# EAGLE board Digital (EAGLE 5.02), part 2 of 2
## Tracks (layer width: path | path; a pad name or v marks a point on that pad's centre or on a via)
D0  (2 unrouted)
  Bottom 1.27: IC3.14 38.57,13.33
D1  (2 unrouted)
  Bottom 1.27: IC3.15 38.57,28.57
D2  (2 unrouted)
  Bottom 1.27: IC3.16 36.03,28.44 | 36.03,28.44 36.03,28.57 | 36.03,28.44 36.03,28.82 | 36.03,28.82 36.03,29.2 | 36.03,29.2 36.41,29.2 36.41,29.08 | 36.41,29.08 36.41,28.06 36.16,27.81 36.16,23.62 35.78,23.62 35.78,28.19 35.65,28.32 35.65,28.95 | 35.65,28.95 35.65,29.2 36.03,29.2 | 36.03,29.2 36.16,29.08 | 36.03,28.82 36.03,28.95 35.65,28.95 | 35.65,28.95 35.65,22.98 36.28,22.98 | 36.28,22.98 36.28,29.08 36.41,29.08 | 36.41,29.08 36.41,22.98 36.28,22.98
D3  (2 unrouted)
  Bottom 1.27: IC3.17 33.49,28.57
E  (via drill 0.7 pad 1.68)  (1 unrouted)
  Bottom 1.27: IC3.6 v18.25,13.33
N$1  (1 unrouted)
  Bottom 1.27: R8.1 D2.A 15.71,34.92 | 36.03,14.6 36.03,14.73 | 36.03,14.73 IC3.13 | 36.03,14.73 36.03,13.96 | 36.03,13.96 36.16,13.96 36.28,14.09 36.28,14.6 | 36.28,14.6 36.28,18.16 35.78,18.16 35.78,13.96 36.03,13.96 | 36.03,13.96 36.28,13.96 36.28,14.6
N$2
  Bottom 1.27: 23.58,44.83 23.58,41.91
N$3
  Bottom 0.254: 0.98,63.88 0.98,63.49 0.85,63.49
N$4  (via drill 0.8 pad 1.68)  (1 unrouted)
  Bottom 1.27: R12.2 51.27,1.9 v55.08,1.9
N$5
  Bottom 1.27: 25.87,16.76 25.87,13.33 24.6,12.06 Q1.2 23.33,12.06 23.33,8.25 C1.2 | 25.87,16.76 IC3.9 | 26,16.12 25.62,16.51 25.62,16.63 | 25.62,16.63 25.62,18.16 26.12,18.16 26.12,10.28 25.23,10.28 | 23.58,11.93 23.2,11.93 23.2,13.08 25.87,13.08 25.87,10.28 25.23,10.28 | 25.23,10.28 23.84,10.28 | 25.87,16.76 25.74,16.63 25.62,16.63 | 25.62,16.63 25.62,12.69
N$6  (1 unrouted)
N$7  (1 unrouted)
N$8  (1 unrouted)
N$9  (1 unrouted)
N$10  (via drill 0.7 pad 1.68)  (4 unrouted)
  Bottom 1.27: IC3.27 8.09,26.66 | 8.09,26.66 v8.09,28.57 8.34,28.57 8.34,26.66 | 8.34,26.66 8.34,23.74 7.84,23.74 7.84,24 | 7.84,24 7.84,28.32 | 7.84,28.32 7.84,28.44 | 7.84,28.32 7.84,29.08 | 8.09,26.66 8.34,26.66 | 8.34,26.66 8.34,29.08 7.96,29.08 | 7.96,24 7.84,24 | 7.84,24 7.84,23.49 8.34,23.49
N$11  (1 unrouted)
  Top 1.27: 34.63,64.13 16.98,64.13 16.98,66.42 | 34.63,64.13 34.76,64.13 34.76,66.67 36.03,67.94 IC1.3 | IC2.1 16.98,66.42 | 16.98,70.1 16.6,70.1 | 16.98,70.1 17.61,70.1 17.61,69.97 | 17.61,69.97 17.61,64.26 | 16.98,70.1 16.98,69.72 | 15.96,70.1 16.98,70.1 | 15.96,65.15 15.96,70.1 | 15.96,65.15 15.96,64 19.27,64 | 19.27,64 35.01,64 | 34.63,64.13 34.89,64.13 35.01,64 | 35.01,64 35.01,65.78 | 35.01,65.78 35.01,66.8 35.27,67.05 36.79,67.05 36.79,70.73 35.14,70.73 35.14,67.18 | 16.98,66.42 16.98,66.29 19.27,64 | 17.49,68.83 17.49,69.84 17.61,69.97 | 17.61,69.97 17.61,70.61 15.96,70.61 15.96,70.1 | 15.96,65.15 16.6,65.15 | 15.96,65.15 15.96,62.61 35.27,62.61 35.27,66.42 | 32.73,63.24 35.01,63.24 | 32.73,63.24 16.6,63.24 | 35.01,65.78 35.01,65.53 32.73,63.24
  Bottom 1.27: 9.36,69.21 IC2.1 C4.+ | IC1.3 R2.2
N$12
  Bottom 1.27: 51.78,72 48.09,72 48.09,70.48
N$13
  Bottom 1.27: 24.22,41.78 26.25,41.78 26.25,43.68 25.11,43.68
N$14
  Bottom 1.27: B1.AC2 9.36,62.86 T1.2.MP
N$15
  Bottom 1.27: T2.1.MP 1.74,46.35 B2.AC1 5.55,50.16 R9.2
N$16
  Bottom 1.27: T2.2.MP 1.74,41.27 B2.AC2 6.82,41.27 6.82,41.02 | R8.2 6.82,41.02 | 6.18,41.14 6.69,41.14 6.82,41.02 | 6.82,41.02 6.82,42.41 6.57,42.41 | 6.57,42.41 0.34,42.41 0.34,36.57 7.2,36.57 7.2,42.41 6.57,42.41
N$17
  Bottom 1.27: 11.39,62.61 11.39,63.62
N$18
  Bottom 1.27: R14.1 63.97,67.94 VT2.2
N$19
  Bottom 1.27: IC3.1 R1.2
N$20  (via drill 0.8 pad 1.68)
  other vias: 27.14,50.16
N$21  (via drill 0.8 pad 1.78)
  other vias: 20.54,19.68
N$22
  Bottom 1.27: R11.1 VT2.1
N$23
  Bottom 1.27: VT3.2 60.8,58.41 60.16,57.78 R16.1
N$24  (via drill 0.7 pad 1.68)  (1 unrouted)
  Bottom 1.27: R10.2 58.89,18.41 v58.89,17.14
N$25
  Bottom 1.27: R19.2 VT3.1 60.29,60.32 60.29,60.83 | 60.29,60.83 55.46,60.83 55.46,60.45 56.1,59.81 59.02,59.81 | 59.02,59.81 59.78,59.81 60.16,60.19 | 59.27,60.7 60.16,60.7 60.29,60.83 | 60.29,60.83 60.67,60.83 60.67,60.45 60.03,59.81 59.02,59.81
N$26
  Top 1.27: 48.6,21.84 46.32,21.84
N$27
  Bottom 1.27: R4.2 19.52,41.27 C3.1 B2.+ 11.9,41.27 11.9,41.52 | 11.9,41.52 11.9,41.91 19.52,41.91 20.79,43.17 21.81,43.17 21.81,42.41 20.54,41.14 | 20.54,41.14 20.41,41.02 11.9,41.02 | 11.9,41.52 11.9,40.63 20.03,40.63 20.54,41.14
N$28
  Bottom 1.27: 24.73,50.03 27.01,47.75 27.01,47.62
N$29
  Bottom 1.27: 10.5,24.63 10.5,23.74 | 10.5,23.74 10.88,23.74 10.88,29.08 10.25,29.08 10.25,24.12 | 10.25,24.12 10.25,23.74 10.5,23.74 | 10.25,24.12 10.25,23.49 10.88,23.49
N$30
  Top 1.27: 50.38,52.45 50.38,52.19 53.05,52.19 53.05,54.86 51.27,54.86 | 50.76,54.86 51.27,54.86 | 51.27,54.86 51.27,52.7 49.87,52.7 51.02,52.57
N$31  (via drill 0.7 pad 1.68)  (1 unrouted)
  Bottom 1.27: R15.2 v36.03,4.44
N$32  (via drill 0.8 pad 1.68)  (1 unrouted)
  Top 1.27: R16.2 50.87,52.2 9.26,52.2 9.36,32.38 10.63,31.11 v10.63,28.57 IC3.26
  Bottom 1.27: IC3.26 v10.63,28.57
N$33
  Bottom 1.27: VT1.3 56.35,69.21 R19.1
N$34
  Bottom 1.27: IC1.2 33.49,65.4 R3.2
N$35
  Bottom 1.27: 13.17,28.7 13.17,29.08 13.42,29.08 13.42,23.62 12.92,23.62 | 12.92,23.62 12.92,29.08 | 13.17,24 13.17,23.87 12.92,23.62 | 12.92,23.62 12.92,23.36 13.42,23.36
N$36
  Bottom 1.016: VT1.1 51.4,69.21 51.4,66.16 D1.C
N$37
  Bottom 1.27: 24.6,42.54 R4.1 | IC3.23 18.25,36.19 24.6,42.54 | 24.6,42.54 24.6,45.08 23.33,46.35 R5.2
N$38
  Bottom 1.27: 28.41,23.87 28.54,23.87 28.54,28.7 28.16,28.7 28.16,28.57 | 28.16,28.57 28.16,24.63 | 28.16,24.63 28.16,23.87 28.28,23.87 | 28.16,24.63 28.16,22.98 28.66,22.98 28.66,28.57 | 28.66,28.57 28.66,28.7 | 28.66,28.57 28.66,29.2 28.16,29.2 28.16,28.57
N$39
  Bottom 1.27: 48.48,71.24 51.4,71.24
N$40
  Bottom 1.27: VT5.1 R.EXTERNAL.MP | R.EXTERNAL.MP D9.A | R23.2 R.EXTERNAL.MP
N$41
  Bottom 0.406: R3.1 40.98,65.4 43.65,69.08 43.65,72.26 | 43.52,72.26 43.65,72.26 | 43.65,72.26 43.65,72.51
  Bottom 1.016: 43.27,72.25 43.27,66.16 D1.A
  Bottom 1.27: R3.1 41.11,65.4 | 31.08,68.7 31.08,67.56 29.55,67.56 29.55,72 30.95,72 | 30.95,72 43.27,72.25 43.52,72.26 | 30.95,72 IC1.1
N$43
  Bottom 1.27: R7.1 6.82,32.38 JP1.2
N$44
  Bottom 1.27: IC3.18 30.95,26.79 | 30.95,26.79 30.95,26.92 | 30.95,26.92 R13.2 | 30.95,26.92 31.08,26.92 31.08,28.44 | 31.08,28.44 31.08,23.87 30.7,23.87 30.7,28.7 31.08,28.7 31.08,28.44 | 30.95,26.79 30.95,23.49 31.08,23.49 31.08,22.98 30.57,22.98 30.57,28.7 | 30.57,28.7 31.2,28.7 31.2,28.44 | 31.2,28.44 31.2,22.98 30.44,22.98 30.44,28.32 | 30.44,28.32 30.44,28.7 30.57,28.7 | 31.08,28.44 31.2,28.44 | 31.2,28.44 31.2,29.2 30.44,29.2 30.44,28.32
N$45
  Bottom 1.27: IC3.28 JP1.1
N$46
  Bottom 1.27: R18.2 IC3.19
N$47
  Bottom 1.27: 38.44,28.32 38.44,23.49 39.84,23.49 39.84,28.06 38.7,29.2 38.19,29.2 38.19,27.93
N$48  (via drill 0.7 pad 1.68)  (1 unrouted)
  Bottom 1.27: R17.1 v65.24,17.14
N$49  (via drill 0.7 pad 1.68)  (1 unrouted)
  Bottom 1.27: R23.1 v60.16,28.57
N$50  (via drill 0.7 pad 1.68)  (1 unrouted)
  Bottom 1.27: VT6.1 v51.27,17.14
N$51  (via drill 0.7 pad 1.68)  (1 unrouted)
  Bottom 1.27: R24.1 68.54,41.27 | 68.54,41.27 v69.05,41.27 | 68.54,41.27 70.45,41.27
N$52  (via drill 0.7 pad 1.68)  (1 unrouted)
  Bottom 1.27: IC3.2 v8.09,13.33
N$53
  Bottom 1.27: 23.2,16.38 23.2,15.87 | 23.2,15.87 23.2,15.74 23.58,15.74 23.58,20.06 | 23.2,15.87 23.08,15.74 22.95,15.74 22.95,19.93
N$54  (via drill 0.8 pad 1.93)
  other vias: 38.57,28.57
N$55
  Bottom 1.27: R2.1 39.84,52.7 K1.1
N$56  (via drill 0.8 pad 1.93)
  other vias: 36.03,28.57
N$57  (via drill 0.8 pad 1.93)
  Bottom 1.27: v33.49,28.57 33.49,29.2 33.62,29.2 | 33.62,29.2 33.87,28.95 33.87,28.82 | 33.87,28.82 33.87,28.32 | 33.87,28.32 33.87,27.93 33.74,27.81 33.74,27.55 33.62,27.43 33.62,23.49 33.11,23.49 33.11,24.89 | 33.11,24.89 33.11,29.2 33.62,29.2 | 33.62,28.32 33.87,28.32 | 33.87,28.32 33.87,27.55 | 33.11,24.89 33.11,22.98 33.87,22.98 33.87,28.82 | 33.87,28.82 33.87,29.2
N$58  (via drill 0.8 pad 1.68)
  other vias: 56.35,6.98
N$59  (via drill 0.8 pad 1.93)
  other vias: 69.05,51.43
N$60  (via drill 0.8 pad 1.93)
  other vias: 1.74,-9.53 1.74,-9.53 1.74,-9.53 1.74,-9.53 1.74,-9.53 1.74,-9.53 61.43,36.19
N$61  (via drill 0.8 pad 1.68)
  other vias: 15.71,28.57
N$62  (via drill 0.7 pad 1.68)
  other vias: 38.57,13.33
N$63  (via drill 0.7 pad 1.68)
  other vias: 15.71,34.92
N$64  (via drill 0.7 pad 1.68)
  other vias: 36.03,14.6
N$65  (via drill 0.7 pad 1.68)
  other vias: 33.49,14.6
N$66  (via drill 0.7 pad 1.68)
  other vias: 43.65,41.27 37.3,41.27
N$67  (via drill 0.7 pad 1.78)
  other vias: 69.05,48.89
N$68
  Bottom 1.27: 0.34,65.27 3.14,65.27 4.03,64.38 10.38,64.38 | 10.38,64.38 10.5,64.38 | 3.77,62.35 3.9,62.48 10.5,62.48 10.5,64.38 | 3.77,62.35 2.76,61.34 0.22,61.34 0.22,65.15 0.47,65.15 1.49,64.13 8.22,64.13 8.85,63.49 3.52,63.49 2.12,62.1 | 10,64.26 10.12,64.38 10.38,64.38 | 10.5,64.38 12.15,64.38 12.15,62.35 3.77,62.35
N$69  (1 unrouted)
  Bottom 1.27: 10.38,59.94 4.66,59.94 | 4.66,59.94 4.41,59.68 | 5.04,59.56 4.66,59.94 | 10.63,59.94 10.63,58.67 10.5,58.67 | 10.5,58.67 4.92,58.67 3.77,57.53 3.77,53.46 0.34,53.46 0.34,59.05 2.12,58.8 2.12,59.05 | T1.1.MP 1.74,59.05 2.12,59.05 | 2.12,59.05 3.77,59.05 | 3.77,59.05 9.36,59.05 | 2.12,59.05 0.6,59.05 | 4.66,59.94 3.77,59.05 | 8.6,58.92 10.5,58.92 10.5,58.67 | 10.5,58.67 12.03,58.67 12.03,60.07 4.79,60.07
N$70
  Bottom 1.27: 10.88,59.68 11.52,59.68 11.52,59.43
N$71
  Bottom 1.27: 1.1,58.29 1.1,54.35 2.76,54.35 2.88,54.48 2.88,58.16 2.76,58.29 3.26,58.29 3.39,58.16
N$72
  Bottom 1.27: 2.76,56.13 4.15,56.13 6.95,58.92
N$73
  Bottom 1.27: 7.2,67.18 7.2,67.81 | 7.2,67.81 7.2,70.35 17.11,70.35 17.11,70.23 | 17.11,67.43 17.11,66.54 7.2,66.54 7.2,67.81 | 17.11,70.23 17.11,67.43 | 17.11,67.43 17.11,59.18 | 17.11,70.23 17.11,71.12 7.07,71.12 7.07,66.54
N$74
  Bottom 1.27: 8.22,69.46 8.22,68.7 | 8.22,67.05 8.22,68.7 | 8.22,68.7 8.98,69.46
N$75
  Bottom 1.27: 9.87,68.32 16.22,68.32
N$76
  Bottom 1.27: 16.34,67.43 12.41,67.43 | 12.41,67.43 9.74,67.43 | 15.08,64.89 12.54,67.43 12.41,67.43
N$77
  Bottom 1.27: 16.98,58.16 15.2,58.16 15.2,66.54 15.08,66.67
N$78
  Bottom 1.27: 15.96,65.78 15.96,59.05
N$79
  Bottom 1.27: 20.03,60.7 20.03,55.75
N$80
  Bottom 1.27: 22.31,58.8 22.31,56.13 22.06,55.88 21.3,55.88 21.04,56.13 21.04,58.8 21.17,58.92
N$81
  Bottom 1.27: 11.9,55.88 9.87,55.88
N$82
  Bottom 1.27: 23.2,52.95 11.9,52.95 | 11.9,52.95 9.61,52.95 | 9.61,50.67 11.9,52.95 | 11.9,52.95 10.88,52.95 10.12,52.19
N$83
  Bottom 1.27: 9.61,54.22 22.57,54.22 22.7,54.1
N$84
  Bottom 1.27: 29.81,59.94 29.81,60.32 28.79,61.34 20.03,61.34
N$85
  Bottom 1.27: 20.03,61.84 20.03,71.12 19.52,71.12 | 19.52,71.12 19.39,71.12 19.39,61.34 | 19.52,70.86 19.52,71.12 | 19.52,71.12 19.27,71.12 19.27,62.23 | 19.27,62.23 19.27,61.21 19.77,60.7 | 19.01,56.26 19.27,56.51 19.27,62.23
N$86
  Bottom 1.27: 21.17,60.45 28.92,60.45 28.92,59.81 21.68,59.81
N$87  (1 unrouted)
  Bottom 1.016: 30.19,63.62 32.09,61.72 41.49,61.72 41.49,60.32
  Bottom 1.27: 21.93,70.1 26.12,70.1 26.63,69.59 26.63,68.19 | 26.63,68.19 26.63,65.78 | 26.63,65.78 26.63,64.13 28.16,64.13 | 26.63,68.19 26.63,69.21 IC2.3 22.06,69.84 21.93,69.97 21.93,70.99 27.01,70.99 27.01,66.54 | 28.16,64.13 29.04,64.13 | 29.04,64.13 29.68,64.13 30.19,63.62 27.27,66.54 27.01,66.54 | K1.S2 57.49,49.02 55.08,51.18 55.08,57.78 52.54,60.32 41.49,60.32 41.24,60.32 41.24,61.59 | 21.93,68.19 26.63,68.19 | 27.01,66.54 27.01,64.51 | 26.63,65.78 26.63,65.65 28.16,64.13 | 29.04,64.13 29.04,64.51 27.01,66.54
N$88
  Bottom 1.27: 16.47,54.48 20.54,58.54 20.54,57.02 19.27,55.75
N$89
  Bottom 1.27: 8.73,54.35 8.73,52.57 8.6,52.45
N$90
  Bottom 1.27: 6.95,50.03 6.95,50.16 7.07,50.29 7.2,50.16 7.2,45.21 0.34,45.21 0.34,50.41 6.95,50.41
N$91
  Bottom 1.27: 6.31,49.65 6.31,46.35
N$92
  Bottom 1.27: 1.23,49.91 1.23,48.25 | 1.23,48.25 1.23,47.37 | 1.23,47.37 1.23,46.1 | 5.04,48.25 1.23,48.25 | 1.23,47.37 4.66,47.37
N$93
  Bottom 1.27: 1.74,49.27 4.92,49.27
N$94
  Bottom 1.27: 52.67,38.86 50.13,38.86 50.13,35.94 53.94,35.94 53.94,37.71 52.79,38.86 51.91,38.86 50.89,37.84 50.89,36.7 53.17,36.7 53.3,36.82 52.41,36.82 51.65,37.59
N$95
  Bottom 1.27: 23.46,20.44 45.55,20.44 46.19,21.08 | 46.19,21.08 47.08,21.97 | 46.19,21.08 46.19,22.35 46.06,22.47 46.06,22.6 46.7,22.6
N$96
  Bottom 1.27: 32.22,38.22 23.84,38.22
N$97
  Bottom 1.27: 26.5,46.1 26.5,49.91 26.63,50.03
N$98
  Bottom 1.27: 17.49,46.22 17.49,47.75 10,47.75 10,47.11 16.73,47.11
N$99
  Bottom 1.27: 11.9,50.03 11.77,50.03 | 11.77,50.03 11.52,50.03 11.52,49.52 18.76,49.52 | 11.77,50.03 11.77,50.16 12.54,50.92 19.01,50.92 19.65,50.29
N$100  (via drill 0.7 pad 1.68)  (1 unrouted)
  Bottom 1.27: 19.65,49.91 19.65,44.95 18.5,43.81 17.87,43.81 | R9.1 D3.A 19.52,50.16 19.52,48.64 | 19.52,48.64 19.52,45.08 18.25,43.81 17.87,43.81 | 17.87,43.81 9.36,43.81 9.36,34.92 v11.9,34.92 | IC3.12 33.49,14.6 | 19.52,48.64 18.12,50.03
N$101
  Bottom 1.27: 16.6,37.33 16.6,38.35 11.39,38.35 11.39,37.08 16.6,37.08
N$102
  Bottom 1.27: 15.71,34.67 15.71,34.41 | 15.71,34.41 16.34,34.41 16.34,37.21 | 15.96,34.67 15.71,34.41 | 15.71,34.41 14.57,34.41 14.57,37.21
N$103
  Bottom 1.27: 16.73,37.21 16.73,38.73 11.27,38.73 11.27,37.08
N$104
  Bottom 1.27: 12.03,35.05 12.54,35.05 12.54,34.41 9.36,34.41 9.36,34.92 9.74,35.3 12.54,35.3
N$105
  Bottom 1.27: 5.55,31.36 5.55,30.98 16.22,30.98 16.22,32.25 15.96,32.51 4.15,32.51 4.03,32.38 4.03,30.86 16.22,30.86 16.09,30.98 16.09,31.74 15.96,31.62 5.8,31.62
N$106
  Bottom 1.27: 6.18,28.7 6.06,28.57 6.06,24.12 | 6.06,24.12 6.06,24 4.03,24 4.15,24.12 4.15,28.7 4.79,28.7 | 4.79,28.7 6.31,28.7 6.31,28.06 5.04,28.06 4.79,27.81 4.79,24.51 4.28,24 3.9,24 3.9,28.7 4.79,28.7 | 6.06,24.12 6.06,23.74 3.9,23.74 | 4.28,24.12 3.9,23.74 | 3.9,23.74 3.9,23.49 6.06,23.49
N$107
  Bottom 1.27: 39.08,54.48 40.48,54.48 40.6,54.35 40.6,43.81 40.48,43.68 31.33,43.68 31.2,43.81 31.2,46.98 33.62,46.98
N$108
  Bottom 1.27: 39.46,53.97 32.09,46.6
N$109
  Bottom 1.27: 38.57,51.3 38.57,54.35 38.7,54.48 38.95,54.48
N$110
  Bottom 1.27: 39.84,51.68 39.59,51.43 39.59,44.7 39.46,44.57 32.35,44.57
N$111
  Bottom 1.27: 33.62,45.46 39.33,45.46
N$112
  Bottom 1.27: 39.2,50.67 34.51,45.97
N$113
  Bottom 1.27: 38.7,45.71 38.7,49.02
N$114
  Bottom 1.27: 37.94,48.64 37.43,48.13 37.43,45.97
N$115
  Bottom 1.27: 37.3,45.97 36.28,46.98 35.65,46.98 36.03,46.6 36.03,46.1
N$116
  Bottom 1.27: 68.54,58.03 66.51,60.07 66.51,60.19
N$117
  Bottom 1.27: 24.35,44.95 24.47,45.08 24.47,46.98 24.22,46.98 | 21.55,46.98 23.84,46.98 | 23.84,46.98 23.96,46.98 23.96,45.08 21.42,45.08 21.42,46.98 | 24.22,46.98 23.84,46.98 | 24.22,46.98 24.6,46.98 24.6,44.57 25.74,43.43
N$118
  Bottom 1.27: 22.31,68.58 22.31,68.45 21.93,68.07 21.93,67.43 22.44,66.92 22.44,64 29.43,64
N$119
  Bottom 1.27: 25.62,64.51 25.62,67.56 23.46,67.56 22.95,67.05 22.95,65.4 23.46,64.89 24.6,64.89 24.6,66.67 24.09,66.67 23.84,66.42 23.84,65.53
N$120
  Top 1.27: 50.76,38.09 51.14,38.09
N$121
  Bottom 1.016: 41.36,64.64 41.36,65.02 42.51,66.16
N$122
  Bottom 1.27: 30.31,71.24 30.19,71.12 30.19,68.7 31.2,68.7 | 31.2,68.19 31.2,68.7 | 31.2,68.7 31.2,71.62 | 31.2,68.7 31.2,67.56
N$123
  Bottom 1.27: 35.9,69.84 35.9,68.19 40.48,68.19 40.98,68.7 40.98,70.1 35.9,70.1
N$124
  Bottom 1.27: 51.65,20.44 51.65,21.59 50.38,21.59
N$125
  Bottom 1.27: 32.98,66.04 32.98,70.35 33.87,70.35 | 33.36,69.97 33.36,70.35 33.87,70.35 | 33.87,70.35 33.87,64.64 31.97,64.64 31.46,65.15 31.46,65.91 33.11,65.91 33.36,66.16
N$126
  Bottom 1.27: 32.6,52.95 33.62,52.95 33.74,53.08
N$127
  Bottom 1.27: 51.78,21.59 51.78,20.31 51.14,20.31 | 51.14,20.31 50.89,20.31 50.89,20.82 | 45.55,20.95 51.02,20.95 51.14,20.82 50.89,20.82 | 50.89,20.82 45.05,20.82 | 51.02,20.57 51.02,20.44 51.14,20.31 | 51.14,20.31 46.06,20.31 45.43,20.95
N$128
  Bottom 1.016: 41.49,64 41.49,63.75 43.78,66.04 43.78,72.39
  Bottom 1.27: 36.66,65.78 36.41,65.78 | 36.41,65.78 36.41,63.88 41.36,63.88 41.49,64 42.76,65.27 42.76,67.18 42.13,67.18 42,67.05 42,66.54 41.24,65.78 36.41,65.78 | 36.41,65.78 36.41,66.16 41.11,66.16
N$129
  Bottom 1.27: 41.11,64.51 37.05,64.51
N$130
  Bottom 1.016: 42.63,66.16 42.63,66.67 42.89,66.92 42.89,71.5
N$131
  Bottom 1.016: 43.27,72.26 43.27,68.45 | 43.27,68.45 43.27,65.65 41.36,63.75 | 40.6,65.65 40.6,65.78 43.27,68.45
N$132
  Bottom 1.016: 51.78,66.16 51.78,65.65 51.91,65.53 51.91,65.27 47.97,65.27 47.97,71.5 48.73,71.5 48.73,66.04 49.49,66.04 49.49,67.05 50.76,67.05 50.76,67.18 50.13,67.18 50.13,66.42 50.89,66.42 50.89,70.1
  Bottom 1.27: 50.25,65.4 51.78,66.92 51.78,69.59 | 51.65,69.97 51.78,70.1 51.78,69.59 | 51.78,69.59 51.78,71.88 | 51.78,69.59 51.78,66.16 51.78,65.53
N$133
  Bottom 1.27: 51.78,70.35 48.09,70.35 48.09,67.18
N$134
  Bottom 1.27: 49.11,69.59 49.11,67.56
N$135
  Bottom 1.27: 50.13,69.72 50.13,67.81
N$136
  Bottom 1.27: 50.25,58.16 50.63,57.78 50.63,57.02 50.13,56.51 50.13,48.89
N$137
  Bottom 1.27: 49.62,58.16 49.62,58.29 49.87,58.54 49.37,58.54 | 49.37,58.54 48.73,58.54 48.73,48.89 50.38,48.89 50.51,49.02 50.51,57.78 | 49.24,58.41 49.37,58.54 | 49.37,58.54 51.27,58.54 51.91,57.91 51.91,56 51.65,56 50.63,54.99
N$138
  Bottom 1.27: 49.75,51.18 49.75,49.78 49.49,49.52
N$139
  Bottom 1.27: 51.02,48.76 48.73,48.76
N$140
  Bottom 1.016: 34.63,54.1 34.63,54.22 34.76,54.35 29.3,54.35
N$141
  Bottom 1.27: 56.22,69.97 56.22,70.23 | 56.22,70.23 56.22,70.35 56.35,70.35 | 56.35,70.35 56.48,70.35 56.48,64.89 54.95,64.89 54.95,66.16 55.59,66.16 | 56.22,70.23 56.35,70.35 | 56.35,70.35 55.84,70.35 55.84,66.42
N$142
  Bottom 1.27: 29.17,39.87 33.49,39.87 33.49,36.06 30.31,36.06 | 31.33,37.59 31.71,37.59 32.6,36.7 32.6,36.06 30.31,36.06 | 30.31,36.06 22.31,36.06
N$143
  Bottom 1.27: 31.84,45.33 31.84,45.59 31.97,45.71
N$144
  Bottom 1.27: 31.71,45.59 31.71,44.06 31.2,43.56 31.2,42.29 33.49,42.29 33.49,43.17 32.22,43.17
N$145
  Bottom 1.27: 36.54,41.78 44.41,41.78 | 44.41,41.78 44.54,41.78 44.54,39.62 36.16,39.62 36.16,41.52 | 36.16,41.52 36.16,41.78 44.41,41.78 | 36.28,41.4 36.16,41.52 | 36.16,41.52 36.16,38.48 44.67,38.48 44.67,41.78
N$146
  Bottom 1.27: 36.28,40.51 43.9,40.51
N$147
  Bottom 1.27: 48.98,30.86 48.86,30.86 47.21,32.51
N$148
  Bottom 1.27: 58,55.37 58,56.13 58.51,56.64
N$149
  Bottom 1.27: 59.78,56.64 60.16,56.64 61.05,57.53
N$150
  Bottom 1.27: 44.54,63.24 44.54,63.75 45.17,63.75 | 45.17,63.75 45.81,63.75 45.81,62.23 43.9,62.23 43.9,63.75 45.17,63.75
N$151
  Bottom 1.27: 69.3,70.23 70.95,70.23 70.95,71.75 70.57,71.75 | 70.57,71.75 65.49,71.75 65.49,70.1 70.95,70.1 | 70.57,71.75 71.08,71.75 arc-90 71.21,71.62 71.21,70.1
N$152
  Bottom 1.27: 65.37,67.43 65.37,64.89 62.57,64.89 62.57,68.19 71.21,68.19 71.21,67.69 66.76,67.69 | 66.76,67.69 65.24,67.69 | 65.11,66.04 66.76,67.69
N$153
  Bottom 1.27: 64.86,67.81 64.86,65.4
N$154
  Bottom 1.27: 63.34,67.94 63.34,65.4
N$155
  Bottom 1.27: 58.64,65.02 59.78,65.02 59.78,67.31 59.14,67.31
N$156
  Bottom 1.27: 69.3,65.65 69.56,65.65 | 69.56,65.65 71.34,65.65 71.34,51.05 67.91,51.05 67.91,65.53 | 68.92,64.77 69.56,64.77 69.56,65.65 | 69.56,65.65 68.03,65.65
N$157
  Bottom 1.27: 70.19,65.15 70.19,51.81
N$158
  Bottom 1.27: 69.3,49.27 71.21,49.27 | 71.21,49.27 71.34,49.27 71.34,45.08 67.91,45.08 67.91,49.27 71.21,49.27
N$159
  Bottom 1.27: 70.19,49.02 70.19,45.84
N$160
  Bottom 1.27: 64.86,41.02 64.86,40.13 71.34,40.13 71.34,42.29 64.73,42.29 64.73,40.13
N$161
  Bottom 1.27: 64.35,45.08 65.11,45.08 | 65.11,45.08 65.37,45.08 65.37,57.02 63.59,57.02 63.59,45.08 63.72,45.08 | 63.72,45.08 65.11,45.08 | 63.72,45.59 63.72,45.08 | 63.72,45.08 62.57,45.08 62.57,51.68 63.34,52.45
N$162
  Bottom 1.27: 64.61,56.64 64.61,45.71
N$163
  Bottom 1.27: 62.83,61.46 66.51,61.46 | 66.51,61.46 67.53,61.46 | 68.16,63.11 66.51,61.46
N$164
  Bottom 1.27: 52.67,29.84 52.79,29.84 54.45,31.49
N$165
  Bottom 1.27: 21.3,34.92 23.71,34.92 23.84,34.79
N$166
  Bottom 1.27: 52.16,46.6 52.03,46.6 50,48.64
N$167
  Bottom 1.016: 30.7,54.22 30.7,59.56 30.82,59.68 30.82,55.11 31.84,54.1
N$168
  Bottom 1.27: 57.24,35.17 57.49,35.17 | 57.49,35.17 62.06,35.17 62.06,36.19 61.81,36.44 | 61.81,36.44 61.68,36.57 61.05,36.57 59.4,38.22 59.4,38.86 56.48,38.86 56.48,35.17 57.49,35.17 | 61.56,35.94 61.56,36.19 61.81,36.44 | 61.81,36.44 59.52,38.73
N$169
  Bottom 1.27: 57.37,38.09 58.76,38.09
N$170
  Bottom 1.27: 57.11,36.57 60.16,36.57
N$171
  Bottom 1.27: 61.05,36.06 57.62,36.06
N$172
  Bottom 1.27: 50.63,7.11 50.63,9.65 | 50.63,9.65 50.76,9.77 56.22,9.77 56.22,6.35 50.51,6.35 50.51,9.52 50.63,9.65
N$173
  Bottom 1.27: 51.14,8.63 55.46,8.63
N$174
  Bottom 1.27: 55.46,7.74 51.14,7.74
N$175
  Bottom 1.27: 46.06,6.35 46.19,6.35 | 46.19,6.35 47.08,6.35 47.21,6.47 47.21,10.54 | 47.21,10.54 47.21,13.71 | 47.21,13.71 47.21,14.22 | 47.08,6.47 46.32,6.47 46.19,6.35 | 46.19,6.35 45.3,6.35 45.3,13.84 46.06,14.6 | 47.21,13.71 52.92,13.71 | 48.86,12.69 48.86,12.19 47.21,10.54
N$176
  Bottom 1.27: 63.59,24.25 71.34,24.25 71.34,36.7 64.86,36.7 64.86,24.51
N$177
  Bottom 1.27: 55.46,28.44 61.43,28.44 61.43,27.43 55.21,27.43 55.21,29.2 61.94,29.2 61.94,27.43 59.78,27.43 59.78,27.55
N$178
  Bottom 1.27: 60.8,56.64 60.92,56.51 60.92,53.59 60.8,53.46 59.78,53.46 | 57.37,54.1 57.37,54.48 | 57.37,54.48 57.37,56.38 59.14,58.16 61.56,58.16 61.56,57.15 58.25,53.84 57.37,53.84 | 57.37,54.48 57.37,53.46 58.89,53.46 | 58.89,53.46 59.02,53.46 59.02,54.86 | 58.89,53.97 58.89,53.46 | 58.89,53.46 59.78,53.46 | 59.78,53.46 60.16,53.46 60.16,56
N$179
  Bottom 1.27: 51.27,28.32 51.4,28.32 | 51.4,28.32 51.91,28.32 | 51.91,28.32 52.16,28.32 | 52.16,28.32 52.41,28.32 52.41,32.13 | 51.52,28.7 51.4,28.7 51.4,28.32 | 51.4,28.32 51.14,28.32 | 51.14,28.32 50.13,28.32 50.13,32 | 51.14,30.48 51.14,28.32 | 51.14,28.32 49.49,28.32 49.49,32 | 51.52,28.44 52.03,28.44 52.16,28.32 | 52.16,28.32 52.79,28.32 | 51.91,28.95 51.91,28.32 | 51.91,28.32 52.92,28.32 52.92,32.63
N$180
  Bottom 1.27: 20.92,22.73 21.04,22.73 23.33,20.44
N$181
  Bottom 1.27: 64.99,21.08 64.99,22.35 68.41,22.35 68.41,14.73 64.73,14.73 64.73,22.35
N$182
  Bottom 1.27: 5.68,17.27 5.68,18.03 | 5.68,18.03 0.6,18.03 0.6,15.62 5.68,15.62 5.68,18.03
N$183
  Bottom 1.27: 5.3,16.25 1.36,16.25
N$184
  Bottom 1.27: 48.22,4.44 50,4.44 50,1.65
N$185
  Bottom 1.27: 48.6,4.19 48.22,4.19 47.97,4.44 47.08,4.44 47.08,0.5 56.48,0.5 56.48,3.3 49.75,3.3
N$186
  Bottom 1.27: 56.35,1.39 47.71,1.39 47.59,1.52
N$187
  Bottom 1.27: 56.1,2.54 47.59,2.54
N$188
  Bottom 1.27: 47.46,3.42 49.24,3.42
N$189
  Bottom 1.27: 59.14,18.16 59.14,18.03 59.27,17.9 60.41,17.9 60.41,15.87 58,15.87 58,18.66
N$190
  Bottom 1.27: 58.76,16.76 59.65,16.76
N$191
  Bottom 1.27: 59.52,17.27 59.52,16.63
N$192
  Bottom 1.27: 56.86,20.57 56.86,21.33 56.48,21.71 55.21,21.71 55.21,20.44 58.25,17.39
N$193
  Bottom 1.27: 57.37,20.31 57.37,21.08 56.73,21.71 55.97,21.71 55.84,21.59
N$194  (via drill 0.6, 0.7 pad 1.68)  (1 unrouted)
  Top 1.27: R20.2 69.05,45.08 67.78,43.81 63.97,43.81 62.7,42.54 62.7,37.46 v61.43,36.19
  Bottom 1.27: 47.33,43.56 48.6,43.56 48.6,46.73 46.32,46.73 46.32,43.68 48.73,41.27 | 47.46,44.06 47.46,42.54 48.73,41.27 | 47.46,44.06 K1.O2 | 48.73,41.27 49.49,41.27 | 49.49,41.27 49.62,41.27 | 49.62,41.27 53.81,41.27 | v61.43,36.19 60.16,37.46 K1.S1 57.49,37.46 53.81,41.14 47.59,41.14 46.32,42.41 46.32,43.3 47.08,44.06 47.46,44.06 | R20.2 v69.05,48.89 | 47.71,43.3 47.71,43.17 49.62,41.27 | 56.6,38.6 53.94,41.27 49.49,41.27
N$195
  Bottom 1.27: 47.97,45.21 48.6,44.57 48.6,41.91
N$196
  Bottom 1.27: 51.91,48.89 52.79,48.89 53.81,47.87 53.81,43.81 53.94,43.68 | 52.67,43.81 53.94,43.81 54.06,43.68 53.94,43.68 | 52.54,43.68 52.67,43.68 | 53.17,43.68 53.17,48.51 50.25,51.43 | 52.29,45.71 52.29,44.57 53.17,43.68 | 53.17,43.68 52.67,43.68 | 52.67,43.68 51.91,43.68 | 51.91,43.68 51.52,43.68 51.52,49.02 | 53.94,43.68 52.67,43.68 | 52.29,44.32 52.29,44.06 51.91,43.68 | 51.91,43.68 51.02,43.68 51.02,48.13 51.14,48.25
N$197
  Bottom 1.27: 46.06,16.89 46.06,16.76 51.52,16.76 51.65,16.89 51.65,17.39 50.76,18.28 45.94,18.28 45.94,16.76
N$198
  Bottom 1.27: 57.75,43.56 58.76,43.56 | 58.76,43.56 58.76,48.89 57.49,50.16 | 57.49,50.16 55.33,52.32 | 58,43.68 58.64,43.68 58.76,43.56 | 58.76,43.56 59.65,43.56 59.65,48 57.49,50.16
N$199
  Bottom 1.27: 57.62,44.7 57.62,44.57 57.11,44.06 57.11,48.51 54.95,50.67 54.95,57.78 54.83,57.91
N$200
  Bottom 1.27: 52.41,13.08 47.59,13.08
N$201
  Bottom 1.27: 64.73,36.44 64.35,36.82 64.22,36.82 64.22,24.51
N$202
  Bottom 1.27: 42.89,15.49 44.28,15.49 44.28,15.74 | 41.87,16.25 44.03,16.25 44.28,16 44.28,15.74 | 44.28,15.74 43.78,15.24 | 43.78,15.24 41.49,15.24 | 41.49,15.24 41.49,16.25 | 41.49,15.24 41.49,14.09 | 43.78,15.24 44.16,15.24
N$203
  Bottom 1.27: 29.3,6.85 29.55,6.85 | 29.55,6.85 29.81,6.6 29.81,4.69 29.17,4.06 16.85,4.06 16.85,8.76 | 16.85,8.76 16.85,10.41 | 29.55,6.85 29.55,7.23 29.43,7.36 24.85,7.36 24.6,7.11 | 16.6,10.41 16.09,10.41 | 16.09,10.41 13.81,10.41 | 16.85,8.76 16.85,9.65 16.09,10.41
N$204
  Bottom 1.27: 25.23,5.96 29.17,5.96
N$205
  Bottom 1.27: 25.36,5.2 29.17,5.2
N$206
  Bottom 1.27: 22.31,7.36 21.3,7.36 | 21.3,7.36 21.04,7.11 21.04,6.35 22.44,6.35 22.44,7.23 | 21.17,6.98 21.3,7.11 21.3,7.36 | 21.3,7.36 24.09,10.15
N$207
  Bottom 1.27: 16.47,10.92 17.23,10.92 | 17.23,10.92 17.23,4.31 | 16.85,10.66 16.98,10.66 17.23,10.92 | 17.23,10.92 14.06,10.92
N$208  (via drill 0.6, 0.7 pad 1.68, 0.8 pad 1.68)  (4 unrouted)
  Top 1.27: VT5.3 47.46,29.84 48.48,28.82 | 48.48,28.82 48.73,28.57 48.73,23.49 47.59,22.35 | 47.59,22.35 47.46,22.22 VT4.3 | C6.- v44.92,62.86 | v16.98,10.79 19.52,10.79 23.33,14.6 v23.33,19.68 | 47.59,22.35 47.33,22.35 47.33,22.6 45.68,22.6 45.68,20.82 49.24,20.82 49.24,29.97 45.55,29.97 45.55,28.82 47.08,28.82 | 48.48,28.82 47.08,28.82 | 47.08,28.82 48.86,27.05
  Bottom 1.016: 29.68,55.24 C5.- | 23.33,59.05 29.04,59.05
  Bottom 1.27: 9.49,46.6 9.49,46.1 9.36,45.97 9.36,46.35 | 44.92,58.54 45.05,58.54 45.55,58.03 45.55,49.27 42.89,49.27 42.89,57.65 43.9,57.65 44.03,57.53 44.03,55.24 | 44.03,55.24 44.03,50.03 | 21.93,33.02 20.41,34.54 20.28,34.54 | 29.43,59.68 30.06,59.68 30.57,59.18 28.03,53.34 | 32.47,38.98 23.96,38.98 22.82,37.84 | 22.82,37.84 22.57,37.59 22.57,36.7 | C3.2 B2.- 9.36,46.35 | 9.36,55.24 9.36,46.35 | 23.33,55.24 D3.C 27.14,50.16 | 23.33,55.24 23.33,59.05 C4.- 19.52,61.59 IC2.2 | 9.36,55.24 9.36,56.51 | 23.33,55.24 13.42,55.24 | 13.42,55.24 9.36,55.24 | 39.2,57.78 38.57,57.78 35.01,54.1 | 39.2,57.78 41.49,57.78 | 41.49,57.78 C6.- 44.92,57.27 | 35.01,54.1 33.49,53.34 28.03,53.34 | 28.03,53.34 29.68,55.24 | 28.41,37.46 D2.C 22.57,36.7 | 28.41,37.46 K1.2 | 44.92,57.27 C7.2 | 69.05,60.32 VT2.3 | 69.05,60.32 VT3.3 62.7,60.57 | 69.05,60.32 C8.1 | C8.1 R21.1 C8.1 | v23.33,19.68 20.92,22.09 | 20.92,22.09 20.79,22.22 IC3.22 20.79,30.6 | 20.79,30.6 R7.2 20.79,34.92 22.57,36.7 | 54.32,14.6 54.45,14.6 54.45,17.14 R10.1 50,22.22 VT4.3 44.92,20.95 24.73,20.95 | 54.32,14.6 53.56,14.6 | 53.56,14.6 VT6.3 R12.3 | 24.6,4.44 C1.1 C2.1 | 28.41,37.46 28.41,44.83 | 28.41,44.83 28.41,46.35 R5.1 27.14,50.16 | 24.6,4.44 IC4.3 v16.98,10.79 13.93,10.79 11.9,8.88 IC4.1 | 24.6,4.44 R15.1 | 69.05,60.32 69.05,51.43 | v23.33,19.68 23.33,18.41 | 23.33,18.41 IC3.8 | v23.33,19.68 24.6,20.95 24.73,20.95 | 62.7,60.57 62.7,61.59 61.43,62.86 v44.92,62.86 | 27.14,50.16 28.66,50.16 | 28.66,50.16 v30.95,50.16 | 8.22,56.76 11.9,56.76 13.42,55.24 | 13.42,55.24 20.15,55.24 20.28,55.37 | 8.22,56.76 8.22,54.99 22.95,54.99 | 30.95,50.41 31.84,50.41 32.35,50.92 | 32.35,50.92 34.51,53.08
  Bottom 1.27: 34.51,53.08 39.2,57.78 | 8.34,56 8.34,56.64 8.22,56.76 | 8.22,56.76 7.84,56.38 7.84,52.19 9.49,50.54 | 31.33,51.3 31.97,51.3 32.35,50.92 | 32.35,50.92 32.35,50.79 31.08,49.52 27.77,49.52 | 27.77,49.52 22.57,49.52 22.57,51.81 | 22.57,51.81 22.57,53.21 | 22.57,36.7 26.63,36.7 | 26.63,36.7 32.35,36.7 | 28.66,50.16 28.66,41.4 | 28.66,41.4 28.66,38.6 | 27.77,49.52 27.77,46.1 27.9,45.97 26.5,45.97 | 32.47,53.46 34.12,53.46 34.51,53.08 | 34.51,53.08 28.79,47.37 28.79,48.64 29.3,49.14 | 68.67,59.81 62.7,59.81 62.7,60.57 | 50.51,12.31 46.82,12.31 | 50.51,12.31 52.03,12.31 54.32,14.6 | 54.32,14.6 54.45,14.47 52.29,12.31 50.51,12.31 | 24.73,20.95 22.31,20.95 | 27.14,20.57 25.49,20.57 23.33,18.41 | 20.79,30.6 21.3,30.6 | 21.3,30.6 24.35,30.6 | 24.35,30.6 24.47,30.73 24.47,35.68 | 21.3,30.6 21.17,30.6 21.17,28.32 | 21.17,28.32 21.17,22.09 | 20.92,22.09 20.92,22.22 | 20.92,22.09 20.28,22.73 20.28,34.41 20.66,34.79 | 20.28,34.54 22.82,37.08 22.82,37.84 | 22.82,37.84 20.28,35.3 20.28,34.54 | 23.71,33.9 26.5,36.7 26.63,36.7 | 41.49,57.78 44.03,55.24 | 44.92,57.27 44.92,58.54 | 44.92,58.54 43.9,58.54 | 53.56,14.6 54.32,15.36 | 21.17,28.32 23.58,30.73 | 21.17,28.32 21.17,29.46 21.68,29.97 | 23.08,30.73 24.22,30.73 24.35,30.6 | 24.35,30.6 24.35,30.35 21.04,27.05 | 30.7,39.49 30.57,39.49 28.66,41.4 | 28.41,44.83 27.9,44.83 26.89,45.84 | 9.36,46.35 9.36,45.84 17.61,45.84 17.61,47.75 | 22.57,51.81 20.92,53.46 | 30.82,53.21 32.6,53.59 35.01,54.1
N$209
  Bottom 1.27: 12.03,4.44 12.15,4.31 | 12.15,4.31 12.15,9.14 | 12.15,4.31 12.15,4.19 | 12.15,3.55 11.14,3.55 11.14,3.68 | 11.14,3.68 11.14,8.12 11.65,8.63 | 12.03,4.31 12.15,4.19 | 12.15,4.19 12.15,3.55 | 12.15,3.55 12.15,2.92 11.14,2.92 11.14,3.68
N$210
  Bottom 1.27: 18.76,4.57 17.36,5.96
N$211
  Bottom 1.27: 14.82,5.07 14.82,8.63 14.31,8.63 14.31,5.2 | 14.82,5.07 14.82,3.17 | 14.82,5.07 14.06,5.07 14.06,2.92 15.08,2.92 15.08,5.07
N$212
  Bottom 1.27: 5.55,6.47 5.55,10.54 3.26,10.54 3.26,8 4.66,6.47 | R22.1 4.28,6.98 4.66,6.47 | 12.15,0 11.77,0 | 12.15,0 40.22,0 | 40.22,0 41.11,0 41.11,13.33 43.65,15.87 VT6.2 | 4.66,6.47 4.79,6.98 8.98,6.98 8.98,0.12 9.11,0 12.15,0 | 8.85,6.47 4.66,6.47 | 42.51,15.11 42.51,0 40.22,0
N$213
  Bottom 1.27: 41.24,13.2 41.24,13.33 41.11,13.46 41.11,16.25 | 41.11,16.25 43.9,16.25 44.03,16.38 44.03,16.76 41.11,16.76 41.11,16.25
N$214  (via drill 0.7 pad 1.68)  (1 unrouted)
  Bottom 1.27: 10.76,18.03 10.88,18.03 | 10.88,18.03 10.88,17.39 | 10.88,17.39 10.88,10.92 8.98,9.01 8.22,9.01 8.22,10.54 9.49,10.54 10.38,11.42 | 10.88,18.03 10.5,18.03 10.5,10.66 | IC3.3 v10.63,13.33 10.63,10.79 10.5,10.66 | 10.5,10.66 R22.2 | 10.88,17.39 11.01,17.52 11.01,18.16 | 11.01,18.16 10.5,18.16 | 11.01,18.16 11.01,11.04
N$215
  Bottom 1.27: 7.96,13.08 7.96,12.69 8.34,12.69 8.34,14.09 8.22,14.22
N$216
  Bottom 1.27: 8.34,14.22 7.2,14.22 7.2,12.57 8.34,12.57
N$217
  Bottom 1.27: 13.17,17.52 13.17,18.16 | 13.17,18.16 13.42,18.16 13.42,12.69 12.79,12.69 12.79,18.16 13.17,18.16
N$218
  Bottom 1.27: 15.58,13.2 15.58,12.69 16.09,12.69 16.09,18.16 15.33,18.16 15.33,12.69
N$219
  Bottom 1.27: 18,12.95 18,12.69 | 18,12.69 18.63,12.69 18.63,17.9 18.38,18.16 18,18.16 18,12.69
N$220
  Bottom 1.27: 8.34,14.35 8.34,18.16 7.71,18.16 7.71,13.58
N$221
  Bottom 1.27: 60.8,13.33 62.57,15.11
N$222
  Bottom 1.27: 19.52,8.38 19.52,7.74 19.39,7.62 18.88,7.62 18.88,8.88 20.54,10.54
N$223
  Bottom 1.27: 33.74,14.47 33.74,14.09 33.87,13.96 | 33.87,13.96 33.11,13.96 33.11,18.28 33.87,18.28 33.87,13.96
N$224
  Bottom 1.27: 38.44,16.89 38.44,18.16 38.95,18.16 38.95,12.82 38.32,12.82 38.32,18.16
N$225
  Bottom 1.27: 23.84,11.17 24.98,11.17
N$226
  Bottom 1.27: 29.43,11.17 29.43,12.06 29.68,12.31 28.92,12.31
N$227
  Bottom 1.27: 53.81,14.98 53.81,15.62 | 53.81,17.65 53.81,15.62 | 53.81,15.62 52.67,14.47
N$228
  Bottom 1.27: 35.27,4.19 35.65,4.19 35.78,4.06 31.84,4.06 31.84,4.31 | 33.74,4.31 31.97,4.31 | 31.97,4.31 31.84,4.31 | 31.84,4.31 31.84,4.69 36.66,4.69 36.66,3.68 35.39,3.68 35.39,4.31 31.97,4.31
N$229
  Bottom 1.27: 24.98,11.04 24.98,9.9 | 24.98,9.9 23.58,8.5 | 24.98,9.9 25.74,10.66
N$230
  Bottom 1.27: 44.16,23.49 44.41,23.49 44.41,23.11 43.02,23.11 43.02,27.93 | VT4.2 44.28,26.66 43.02,27.93 | 43.02,27.93 38.57,32.38 R13.1
N$231
  Bottom 1.27: 10.88,0.12 9.23,1.77
N$232
  Bottom 1.27: 25.74,24.25 26,24.25 26,22.98 25.36,22.98 25.36,26.03 26.25,26.03 26.25,25.27 | 26.25,25.27 26.25,22.98 | 25.74,25.14 26.25,25.14 26.25,25.27 | 26.25,25.27 26.25,26.79 | 26.25,26.79 26.25,27.17 25.11,27.17 25.11,26.54 | 25.11,26.54 25.11,22.98 | 25.74,26.79 26.25,26.79 | 26.25,26.79 26.25,28.19 25.11,28.19 25.11,26.54
N$233
  Bottom 1.27: 18.38,26.41 18.5,26.41 18.5,23.74 | 18.5,23.74 18,23.74 18,26.41 | 18.5,23.74 18.5,23.36 17.87,23.36 17.87,26.28
N$234
  Bottom 1.27: 31.46,32.25 31.46,31.36 | 31.46,31.36 30.57,31.36 30.57,32.51 30.82,32.51 | 30.82,32.51 31.46,32.51 | 30.82,32.38 30.82,32.51 | 30.82,32.51 31.58,32.51 | 31.33,31.74 31.33,31.49 31.46,31.36 | 31.46,31.36 39.33,31.36
N$235
  Bottom 1.27: 52.92,9.39 52.92,9.9 56.73,13.71 56.73,12.57 54.83,10.66 55.97,10.66
N$236
  Bottom 1.27: 61.94,13.71 62.7,13.71 62.7,12.95 57.62,12.95
N$237
  Bottom 1.27: 59.27,13.33 59.27,13.08 56.6,10.41
N$238
  Bottom 1.27: 56.48,8.63 56.6,8.63 61.18,13.2
N$239
  Bottom 1.27: 50,29.08 49.24,28.32 48.6,28.32 48.6,32.25 | 56.22,32.25 56.22,32.51 | 56.22,32.51 56.22,33.14 45.94,33.14 45.94,32.25 48.6,32.25 | 48.6,32.25 56.1,32.25 | 56.22,32.51 56.22,33.4 45.94,33.4 | 54.95,32.51 56.22,32.51 | 56.22,32.51 56.22,31.74 53.17,31.74
N$240
  Bottom 1.27: 18.12,20.82 18.25,20.82 18.38,20.7 0.6,20.7
N$241
  Bottom 1.27: 18.38,20.31 0.72,20.31 0.6,20.44
N$242
  Bottom 1.27: 10.88,23.62 10.88,23.36 10.25,23.36
N$243
  Bottom 1.27: 8.22,23.87 8.22,23.49 8.34,23.36 7.84,23.36
N$244
  Bottom 1.27: 5.8,23.87 5.8,23.62 6.06,23.36 3.9,23.36
N$245
  Bottom 1.27: 18.5,17.52 18.63,17.65 18.63,18.16
N$246
  Bottom 1.27: 59.4,12.57 62.7,12.57
N$247
  Bottom 1.27: 28.79,12.44 28.92,12.57 28.92,18.03 28.28,18.03 28.28,14.35
N$248
  Bottom 1.27: 30.82,17.77 30.82,18.28 | 30.82,18.28 31.2,18.28 31.2,13.08 | IC4.2 R6.2 14.44,3.17 | 14.44,3.17 15.71,1.9 38.57,1.9 38.57,5.71 31.2,13.08 | IC3.11 30.95,13.33 31.2,13.08 | 14.57,3.3 14.44,3.17 | 14.44,3.17 14.06,3.55 14.06,4.69 | 31.08,18.03 30.82,18.28 | 30.82,18.28 30.82,15.62
N$249
  Bottom 1.27: 35.52,3.8 35.39,3.68 31.84,3.68
N$250
  Bottom 1.27: 62.57,13.08 62.57,12.95 62.7,12.82
N$251
  Bottom 1.27: 21.68,61.08 21.68,61.21 20.41,62.48
N$252
  Bottom 1.27: 43.65,30.86 43.02,30.86 43.02,30.98 42.25,31.74 | 43.52,31.36 42.63,31.36 42.25,31.74 | 42.25,31.74 39.97,34.03 39.97,34.16 41.62,34.16 44.03,31.74
N$253
  Bottom 1.27: 44.41,30.98 43.52,30.09 43.65,30.09 | 43.65,30.09 44.54,30.09 44.54,31.24 | 44.16,31.24 44.41,31.24 44.41,31.62 43.4,31.62 43.4,30.35 44.54,30.35 44.54,31.24 | 44.54,31.24 44.54,31.62 | 43.65,30.6 43.65,30.09 | R18.1 28.41,34.16 28.92,34.16 | 28.92,34.16 39.71,34.16 | 39.71,34.16 39.84,34.16 43.65,31.11 VT5.2 | 28.92,34.03 28.92,34.16 | 28.92,34.16 27.39,34.16 27.39,31.36 28.92,31.36 28.92,33.78 | 43.65,30.09 43.65,30.22 39.71,34.16
N$254
  Bottom 1.27: 46.57,24.63 46.32,24.63 46.19,24.51 46.06,24.51 | 59.91,20.95 59.91,20.31 60.03,20.31 | 60.03,20.31 60.67,20.31 60.67,23.49 58.89,25.27 | 58.89,25.27 46.06,25.27 | 46.06,25.27 46.06,24.76 46.32,24.51 59.14,24.51 | VT4.1 R.SELF.MP D8.A 58.38,24.76 | R17.2 60.16,22.22 | 60.16,22.22 60.16,23.49 59.65,24 | 59.65,24 59.14,24.51 | 59.14,24.51 58.89,24.76 58.38,24.76 | 60.03,20.31 59.78,20.31 59.78,23.74 | 59.65,24 57.62,24 | 57.62,24 50.89,24 50.63,24.25 | 60.16,22.22 59.4,22.22 57.62,24 | 46.06,24.51 46.06,25.27 | 58.38,24.76 58.89,25.27 | 58.89,25.27 58.51,25.65 46.19,25.65 46.06,25.52 46.06,24.51
N$255
  Bottom 1.27: 66,70.23 65.49,70.23 65.37,70.1 64.86,70.1 64.86,71.75 65.24,71.75
N$256
  Bottom 1.27: 26.89,38.48 26.89,38.6 28.79,40.51
N$257
  Bottom 1.27: 52.16,20.06 52.16,21.84 50.25,21.84
N$258
  Bottom 1.27: 29.04,58.03 30.06,58.03 30.06,55.24
N$259
  Bottom 1.27: 53.68,68.32 53.43,68.32 | 53.43,68.32 53.43,72.13 | 53.43,68.32 53.43,67.69 54.19,67.69 54.19,72.13
N$260
  Bottom 1.27: 53.94,71.12 53.94,71.24 54.83,72.13
N$261
  Bottom 1.27: 30.7,57.27 30.7,59.68 29.04,61.34
N$262
  Bottom 1.27: 43.9,57.91 38.7,57.91
N$263
  Top 1.27: 52.79,38.98 52.67,38.98 | 52.67,38.98 50.76,38.98 | 53.17,38.98 53.17,36.44 50.38,36.44 50.38,37.71 | VT1.2 53.81,59.05 55.08,57.78 55.08,51.05 50.38,46.35 50.38,39.62 | 52.67,37.33 K1.P1 50.38,39.62 | 52.29,37.33 50.38,37.33 50.38,37.71 | 50.38,37.71 50.38,39.62 | 52.67,38.98 53.17,38.98 | 53.17,38.98 53.17,41.27 50.89,41.27 50.89,41.4 51.14,41.4 51.14,39.87 52.29,39.87 52.29,40.38
  Bottom 1.27: VT1.2 53.81,72.13 58.89,72.13 R14.2 58.89,65.15 58.51,65.15 58.51,71.88
N$264  (via drill 0.8 pad 1.78)
  other vias: 50.63,37.46
N$265
  Top 1.27: 52.54,37.21 53.17,37.21 53.17,36.19 | 53.17,36.19 50.38,36.19 | 50.38,36.19 50.38,36.32 | 50.38,36.19 50.38,36.06 53.17,36.06 53.17,36.19
N$266
  Top 1.27: 47.59,22.73 48.86,24 48.98,24
N$267
  Top 1.27: 48.35,22.98 48.35,28.32 48.22,28.19 45.55,28.19 45.55,28.7
N$268
  Top 1.27: 48.48,27.05 47.33,28.19 47.33,28.32
N$269
  Top 1.27: 60.92,35.55 60.92,35.05 | 60.92,35.05 63.08,35.05 63.08,41.91 64.86,43.68 64.86,43.43 70.45,43.43 70.45,47.37 67.65,47.37 67.65,44.06 | 61.94,35.3 61.18,35.3 60.92,35.05 | 60.92,35.05 60.29,35.05 60.29,37.71 62.32,37.71
N$270
  Top 1.27: 68.41,46.86 68.41,45.97 | 68.41,45.97 68.41,45.46 68.16,45.21 | 68.41,45.97 68.29,45.97 66,43.68
N$271
  Top 1.27: 69.43,43.94 69.43,46.1 69.81,46.48
N$272
  Top 1.27: 61.18,37.33 61.3,37.33 62.95,38.98
N$273
  Top 1.27: 51.65,41.02 51.65,41.14 50.51,42.29
N$274
  Top 1.27: 60.92,45.71 64.73,45.71 64.73,48 59.91,48 59.91,41.91
N$275
  Top 1.27: 64.22,47.24 60.54,47.24 60.54,47.11
N$276
  Top 1.27: 60.41,46.86 60.67,46.86 60.67,46.22
N$277
  Top 1.27: 55.46,40.76 60.41,40.76 60.41,44.57 | 60.41,44.57 60.41,45.84 | 60.41,44.57 61.81,45.97 61.94,45.97
N$278
  Bottom 1.27: 38.32,27.93 38.32,27.81 38.19,27.81 38.19,22.98 39.97,22.98 39.97,27.93
N$279
  Top 1.27: 44.03,40.63 44.03,43.17 43.27,43.17 43.27,41.4 43.4,41.4
N$280
  Top 1.27: 16.22,11.17 16.22,11.42 | 16.22,11.42 19.9,11.42 19.9,10.03 15.84,10.03 15.84,11.3 15.96,11.3 15.96,11.42 | 15.96,11.42 15.84,11.42 | 15.96,11.42 16.22,11.42
N$281
  Top 1.27: 23.2,19.93 23.2,20.19 23.96,20.19 23.96,14.85 19.77,10.66
N$282
  Top 1.27: 23.46,20.06 23.08,20.06 22.95,20.19 22.95,13.96
N$283
  Top 1.27: 50.76,54.99 51.91,54.99 51.91,54.73 50.76,54.73 50.76,53.34 51.52,53.34 51.52,54.22
N$284
  Bottom 1.27: 21.17,18.28 21.17,19.68 20.66,20.19 19.14,20.19
N$285
  Bottom 1.27: 17.49,20.82 18.12,20.82 18.63,20.31
N$286
  Bottom 1.27: 23.58,11.68 23.2,11.68 23.2,9.01
N$287
  Bottom 1.27: 41.62,0.38 41.62,13.71 42,13.71
N$288
  Bottom 1.27: 14.69,3.68 14.69,2.66 14.06,2.66 14.06,1.9 15.46,1.9
N$289
  Top 1.27: 15.46,28.57 15.46,29.2 22.82,29.2 | 15.58,28.95 15.58,28.57 15.46,28.57 | 15.46,28.57 15.46,27.93 23.46,27.93 23.46,30.48 | 23.46,30.48 23.46,33.65 | 21.81,28.95 21.93,28.95 23.46,30.48
N$290
  Bottom 1.27: 28.54,14.09 28.28,14.09 28.28,10.28 28.41,10.28 | 28.41,12.06 IC3.10 | 29.68,10.28 29.68,9.52 | 29.68,9.52 31.71,7.49 | 31.71,7.49 C2.2 | 28.41,12.06 Q1.1 29.68,12.06 29.68,10.28 | 28.41,12.06 28.41,10.28 | 28.41,10.28 29.68,10.28 | 31.71,7.49 31.71,6.47 33.36,6.47 33.36,7.62 31.97,7.62 | 29.68,9.52 28.66,10.54
N$291
  Top 1.27: 49.24,49.27 49.24,49.14 47.84,47.75
N$292
  Top 1.27: 10.12,29.33 11.01,29.33 11.01,23.49 10.88,23.36 9.87,23.36 9.87,31.49
N$293  (via drill 0.7 pad 1.68)
  Top 1.016: R20.1 59.91,46.35 59.91,40.89 55.33,40.89 55.33,34.28 43.65,34.28 43.65,40.38 | 43.65,41.4 43.65,41.27 | 43.65,41.27 43.65,40.38 | 43.65,40.38 43.9,40.38 | 43.65,40.38 43.14,40.38 43.14,43.3 44.16,43.3 44.16,40.63 43.65,40.63 43.65,41.27
  Top 1.27: 35.9,38.22 35.9,42.54 | 35.9,38.22 37.68,38.22 37.68,44.83 36.03,44.83 36.03,42.54 | 36.03,42.54 36.03,38.35 35.9,38.22 | 35.9,38.22 35.9,44.83 | v15.71,28.57 23.33,28.57 23.33,33.65 30.95,41.27 34.76,41.27 | 34.76,41.27 34.89,41.27 | 34.89,41.27 v37.3,41.27 | 36.03,42.54 36.03,42.41 34.89,41.27 | 36.28,39.49 36.28,39.75 34.76,41.27
  Bottom 1.016: R20.1 R21.2
  Bottom 1.27: 15.71,28.32 IC3.24 | 15.71,28.32 v15.71,28.57 | v37.3,41.27 43.65,41.27 | 15.71,28.32 15.71,29.08 15.84,29.08 | 15.84,29.08 16.09,29.08 16.09,23.74 15.46,23.74 15.46,23.87 | 15.46,23.87 15.46,29.08 15.84,29.08 | 15.84,24 15.58,24 15.46,23.87 | 15.46,23.87 15.46,23.36 16.09,23.36 | R21.2 C8.2 R21.2
N$294
  Top 1.27: 43.52,64 46.19,64 46.19,57.65 | 46.19,57.65 46.19,56.76 43.9,56.76 43.9,63.62 43.52,64 | 43.52,64 43.52,56.64 46.19,56.64 46.19,57.65
N$295
  Top 1.27: 53.68,70.1 53.68,70.35 53.43,70.61 54.32,70.61 54.32,67.69 53.3,67.69 53.3,70.48
N$296
  Top 1.27: 60.16,71.62 63.21,71.62 63.21,68.96 59.52,68.96 59.4,69.08 59.4,72.26
N$297
  Top 1.27: 59.91,70.86 62.7,70.86
N$298
  Top 1.27: 62.57,70.1 60.16,70.1
N$299  (via drill 0.7 pad 1.68)  (2 unrouted)
  Top 1.27: 59.52,71.5 59.52,72.39 58.89,72.39 | 12.92,29.08 13.55,29.08 13.55,28.82 | 58.89,72.39 R11.2 | 58.89,72.39 4.28,72.39 4.28,36.19 3.01,34.92 3.01,23.49 5.55,20.95 11.52,20.95 | 11.52,20.95 11.9,20.95 13.17,22.22 13.17,22.85 | 13.17,22.85 v13.17,28.57 | 13.55,28.82 13.55,20.95 | 13.55,20.95 11.52,20.95 | 13.55,28.82 13.55,28.95 12.92,28.95 12.92,21.46 | 13.17,22.85 13.17,22.6 11.52,20.95 | 13.04,21.59 13.04,21.46 13.55,20.95 | 13.55,20.95 13.55,20.44 5.42,20.44 2.88,22.98 2.88,34.79
  Bottom 1.27: IC3.25 v13.17,28.57
N$300
  Top 1.27: 36.66,44.32 36.66,39.11 36.92,38.86
N$301
  Top 1.27: 59.65,41.14 59.52,41.02 55.46,41.02 55.46,41.4 59.65,41.4
N$302
  Top 1.27: 51.52,54.99 52.92,54.99
N$303
  Bottom 0.254: -0.04,-1.15 2.5,-1.15 | 2.5,-1.15 72.73,-1.15 72.73,73.15 -0.67,73.15 | -0.67,73.15 -0.93,73.15 | -0.67,73.15 -1.05,73.15 -1.05,-1.15 2.5,-1.15
N$304
  Bottom 0.254: 0.85,62.23 0.85,61.97 1.1,61.97 1.1,62.1 | 1.1,62.1 1.36,62.1 1.36,62.35 0.98,62.35 0.98,63.49 1.49,63.49 1.49,63.24 1.1,63.24 1.1,62.1 | 1.1,62.1 0.98,62.1
N$305
  Bottom 1.016: 42,72.13 43.02,71.12
N$306
  Top 0.254: 2.76,73.15 -1.05,73.15 -1.05,-1.15 -0.42,-1.15 | -0.8,-1.15 -0.42,-1.15 | -0.42,-1.15 72.73,-1.15 72.73,73.15 61.18,73.15
N$307
  Bottom 1.016: 29.93,67.94 29.93,70.61
N$311
  Bottom 1.016: 30.06,52.32 32.85,52.32
N$312
  Top 1.016: 50.63,53.84 50.63,55.11 53.17,55.11
N$313
  Bottom 1.016: 32.47,59.81 32.47,59.68 | 32.47,59.68 32.47,56.26 32.73,56 34.12,56 37.55,59.43 37.55,60.19 32.47,60.19 32.47,59.68 | 32.47,59.68 32.47,57.53 33.36,56.64 34,56.64 36.92,59.56 33.24,59.56 33.24,57.65 33.74,57.15 33.74,57.4 35.65,59.3 34.51,59.3 33.62,58.41
N$314  (via drill 0.7 pad 1.78, 0.8 pad 1.93)  (3 unrouted)
  Top 1.016: 49.75,57.15 49.75,56.89 52.29,56.89 52.29,57.78 50.76,59.3 48.35,59.3 48.35,55.75 | C5.+ 36.16,58.16 37.55,59.56 37.55,59.81 | 37.55,59.81 37.55,60.19 37.05,60.19 | 37.05,60.19 32.47,60.19 32.47,56.26 32.73,56 33.74,56 | 33.74,56 34,56 36.03,58.03 35.01,58.03 33.62,56.64 33.24,56.64 33.11,56.76 33.11,59.56 36.66,59.56 36.66,59.3 36.03,58.67 33.62,58.67 33.62,57.65 39.33,57.65 42.76,54.22 46.82,54.22 48.35,55.75 | 48.35,55.75 49.49,56.89 49.49,57.65 49.62,57.78 C6.+ | 37.3,59.81 37.55,59.81 | 37.55,59.81 37.55,56 36.92,56 | 36.92,56 33.74,56 | 33.74,56 33.74,56.64 36.79,56.64 36.79,58.8 37.43,58.8 | 36.79,59.68 36.79,59.94 37.05,60.19 | 37.05,60.19 39.33,60.19 39.33,56 38.7,56 | 38.7,56 36.92,56 | 36.92,56 36.92,56.76 38.44,56.76 38.44,59.56 38.32,59.56 | 38.7,56.26 38.7,56 | 38.7,56 40.73,56
  Top 1.27: 49.87,49.14 50.38,49.14 50.76,49.52 | 48.86,48.38 48.86,50.29 50.89,50.29 50.89,49.52 50.76,49.52 | 20.92,16.12 20.92,15.74 21.04,15.62 | 21.04,15.62 21.04,20.95 | 20.03,15.62 21.04,15.62 | 50,49.52 50,48.89 48.73,47.62 39.84,47.62 39.84,34.92 27.14,34.92 25.87,33.65 v25.87,27.3 IC3.20 25.87,23.49 24.6,22.22 23.71,22.22 | 50,49.52 C7.1 | 23.71,22.22 22.06,22.22 20.79,20.95 | IC3.7 20.79,20.95 | 20.03,15.62 20.03,20.19 20.79,20.95 | 20.03,15.62 20.03,14.73 20.15,14.73 21.04,15.62 | 50,49.52 50.76,49.52 | 23.71,22.22 26.38,22.22 26.38,23.24 | 25.36,22.73 26.38,22.73 26.38,23.24 | 26.38,23.24 26.38,28.19 25.23,28.19 25.23,22.73
  Bottom 1.27: 19.65,20.06 19.52,20.06 18.38,21.2 17.61,21.2 | C6.+ C7.1 52.54,47.62 K1.P2 57.62,41.27 60.16,41.27 R24.2 D9.C R.MP | R.MP D8.C 63.97,24.76 62.7,23.49 62.7,13.84 56.98,13.84 56.98,6.22 51.27,6.22 | R6.1 20.79,9.52 20.79,15.74 | 18.76,20.44 18.25,20.95 3.01,20.95 | 18.76,20.44 20.79,18.41 IC3.7 20.79,15.74 | R.MP v69.05,28.57 | 56.35,6.98 R12.1 51.27,6.22 | R1.1 3.01,20.95 | 3.01,20.95 0.6,20.95 0.6,22.6 | 0.6,22.6 0.6,22.73 | 0.6,22.6 1.61,21.59 | 51.27,6.22 50.51,6.22 | 18.76,20.44 18,21.2 17.61,21.2 | 17.61,21.2 2.25,21.2 2.25,22.98 1.36,22.98 | 1.36,22.98 0.6,22.98 | 1.36,22.98 3.14,21.2 | 20.79,15.74 21.17,15.74 21.17,18.16 20.54,18.16 20.54,16.25 | 20.54,16.25 20.54,15.87 | 20.54,16.25 20.54,15.74
N$315
  Top 1.016: 48.98,59.05 48.98,57.53 | 48.98,57.02 48.98,57.27 | 48.98,57.27 48.98,57.53 | 48.98,57.53 49.49,58.03 51.14,58.03 51.52,57.65 49.37,57.65 48.98,57.27
N$316  (via drill 0.6)
  other vias: 37.05,59.3
N$317  (via drill 0.6)
  other vias: 52.16,57.53
RS  (via drill 0.7 pad 1.68)  (1 unrouted)
  Bottom 1.27: IC3.4 v13.17,13.33
RW  (via drill 0.7 pad 1.68)  (1 unrouted)
  Bottom 1.27: IC3.5 v15.71,13.33
(copper drawn outside any net)
  shapes: Bottom area x8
